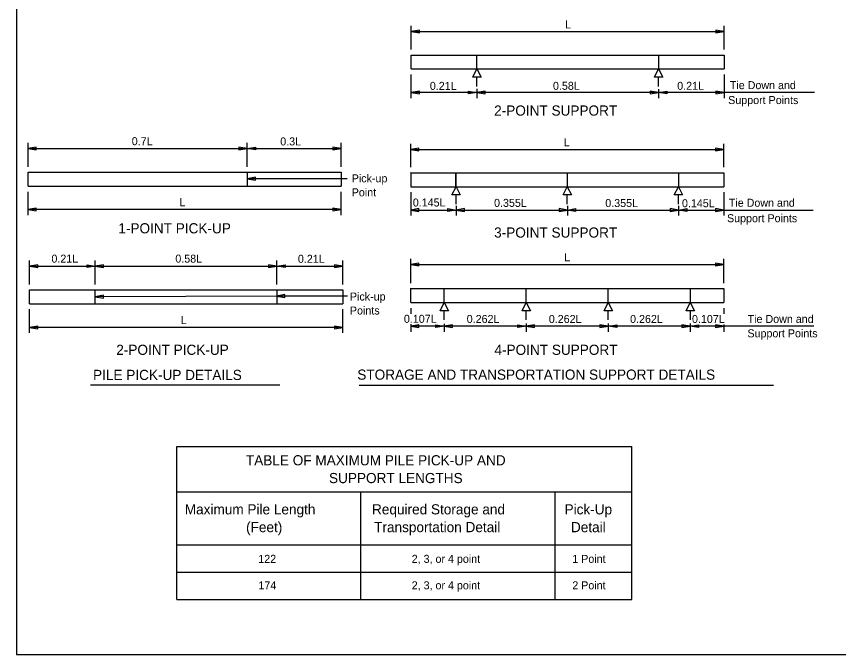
# Model space of a CAD drawing. Extents: x 120462 to 120592, y 120515 to 120635.
# Drawn here: x 120521.21 to 120541.92, y 120603.22 to 120619.3 of the extents above; entities that cross this region are included whole.
import ezdxf

# ---------------------------------------------------------------- set-up
doc = ezdxf.new("R2010")
doc.units = 0
for name, color, linetype in [('ActivePts-ConstElements', 7, 'Continuous'), ('AdhocPoint_dp', 7, 'Continuous'), ('Border', 7, 'Continuous'), ('PlotBorder_dp', 7, 'Continuous')]:
    doc.layers.add(name, color=color, linetype=linetype)

msp = doc.modelspace()

# ---------------------------------------------------------------- linework, layer by layer
at = {"layer": 'ActivePts-ConstElements'}
msp.add_lwpolyline([(120521.209, 120603.217), (120562.259, 120603.217), (120562.259, 120629.163), (120521.209, 120629.163)], close=True, dxfattribs=at)
at = {"layer": 'AdhocPoint_dp'}
for p, q in [((120531.151, 120618.464), (120531.151, 120619.058)), ((120531.151, 120618.918), (120539.041, 120618.918)), ((120539.041, 120618.464), (120539.041, 120619.058)), ((120531.151, 120617.24), (120531.151, 120617.836)), ((120539.041, 120617.836), (120539.041, 120617.24)), ((120532.81, 120617.536), (120532.81, 120617.768)), ((120537.386, 120617.536), (120537.386, 120617.768)), ((120532.808, 120617.47), (120532.808, 120617.24)), ((120537.385, 120617.468), (120537.385, 120617.24)), ((120541.313, 120617.38), (120531.151, 120617.38)), ((120521.501, 120615.509), (120521.501, 120616.109)), ((120521.501, 120615.969), (120529.39, 120615.969)), ((120527.023, 120615.509), (120527.023, 120616.109)), ((120529.39, 120615.509), (120529.39, 120616.109)), ((120531.141, 120615.496), (120531.141, 120616.084)), ((120539.03, 120615.496), (120539.03, 120616.084)), ((120531.141, 120615.944), (120539.03, 120615.944)), ((120531.141, 120615.356), (120531.141, 120615.364)), ((120532.283, 120615.356), (120532.283, 120615.359)), ((120535.085, 120615.356), (120535.085, 120615.362)), ((120529.54, 120615.208), (120527.023, 120615.208)), ((120521.501, 120614.291), (120521.501, 120614.88)), ((120529.39, 120614.291), (120529.39, 120614.881)), ((120531.141, 120614.867), (120531.141, 120614.279)), ((120532.286, 120614.567), (120532.286, 120614.799)), ((120535.086, 120614.567), (120535.086, 120614.799)), ((120537.888, 120614.567), (120537.888, 120614.799)), ((120539.03, 120614.867), (120539.03, 120614.279)), ((120532.285, 120614.522), (120532.285, 120614.279)), ((120535.088, 120614.522), (120535.088, 120614.279)), ((120537.89, 120614.522), (120537.89, 120614.279)), ((120529.39, 120614.431), (120521.501, 120614.431)), ((120531.141, 120614.419), (120541.285, 120614.419)), ((120521.538, 120612.545), (120521.538, 120613.144)), ((120523.195, 120612.545), (120523.195, 120613.144)), ((120527.771, 120612.545), (120527.771, 120613.144)), ((120529.428, 120612.545), (120529.428, 120613.144)), ((120531.141, 120612.578), (120531.141, 120613.185)), ((120539.03, 120612.578), (120539.03, 120613.185)), ((120521.538, 120613.004), (120529.428, 120613.004)), ((120531.141, 120613.045), (120539.03, 120613.045)), ((120531.141, 120612.438), (120531.141, 120612.446)), ((120535.085, 120612.438), (120535.085, 120612.445)), ((120527.761, 120612.252), (120523.195, 120612.235)), ((120529.546, 120612.252), (120527.761, 120612.252)), ((120532.283, 120612.438), (120532.283, 120612.441)), ((120521.538, 120611.321), (120521.538, 120611.917)), ((120529.428, 120611.321), (120529.428, 120611.917)), ((120531.141, 120611.95), (120531.141, 120611.801)), ((120531.986, 120611.65), (120531.986, 120611.881)), ((120534.053, 120611.65), (120534.053, 120611.881)), ((120536.12, 120611.65), (120536.12, 120611.881)), ((120538.188, 120611.65), (120538.188, 120611.881)), ((120539.03, 120611.95), (120539.03, 120611.799)), ((120529.428, 120611.461), (120521.538, 120611.461)), ((120531.141, 120611.545), (120531.141, 120611.353)), ((120541.298, 120611.493), (120531.141, 120611.493)), ((120531.985, 120611.548), (120531.985, 120611.353)), ((120531.985, 120611.418), (120531.985, 120611.353)), ((120534.051, 120611.561), (120534.051, 120611.353)), ((120536.118, 120611.561), (120536.118, 120611.353)), ((120538.185, 120611.559), (120538.185, 120611.353)), ((120539.03, 120611.531), (120539.03, 120611.353)), ((120536.121, 120611.353), (120536.121, 120611.353)), ((120527.847, 120610.008), (120523.078, 120610.008)), ((120529.843, 120610.002), (120540.285, 120610.002)), ((120525.253, 120608.457), (120536.712, 120608.457)), ((120525.253, 120604.606), (120525.253, 120608.457)), ((120536.712, 120604.606), (120536.712, 120608.457)), ((120525.253, 120607.321), (120536.712, 120607.321)), ((120529.883, 120604.606), (120529.883, 120607.321)), ((120534.778, 120604.606), (120534.778, 120607.321)), ((120525.253, 120605.985), (120536.712, 120605.985)), ((120525.253, 120605.296), (120536.712, 120605.296)), ((120525.253, 120604.606), (120536.712, 120604.606))]:
    msp.add_line(p, q, dxfattribs=at)
for points in [[(120531.151, 120618.918), (120531.36, 120618.883), (120531.36, 120618.953)], [(120539.041, 120618.918), (120538.833, 120618.953), (120538.833, 120618.883)], [(120532.808, 120617.976), (120532.913, 120617.768), (120532.703, 120617.768)], [(120537.385, 120617.976), (120537.49, 120617.768), (120537.28, 120617.768)], [(120531.151, 120617.38), (120531.36, 120617.345), (120531.36, 120617.415)], [(120532.808, 120617.38), (120532.6, 120617.345), (120532.6, 120617.415)], [(120532.808, 120617.38), (120533.016, 120617.345), (120533.016, 120617.415)], [(120537.385, 120617.38), (120537.176, 120617.415), (120537.176, 120617.345)], [(120537.385, 120617.38), (120537.593, 120617.415), (120537.593, 120617.345)], [(120539.041, 120617.38), (120538.833, 120617.415), (120538.833, 120617.345)], [(120521.501, 120615.969), (120521.71, 120615.934), (120521.71, 120616.004)], [(120527.023, 120615.969), (120526.815, 120616.004), (120526.815, 120615.934)], [(120527.023, 120615.969), (120527.231, 120616.004), (120527.231, 120615.934)], [(120529.39, 120615.969), (120529.182, 120616.004), (120529.182, 120615.934)], [(120531.141, 120615.944), (120531.35, 120615.909), (120531.35, 120615.979)], [(120539.03, 120615.944), (120538.821, 120615.979), (120538.821, 120615.909)], [(120527.023, 120615.208), (120527.231, 120615.172), (120527.231, 120615.243)], [(120532.285, 120615.007), (120532.39, 120614.799), (120532.18, 120614.799)], [(120535.085, 120615.007), (120535.19, 120614.799), (120534.98, 120614.799)], [(120537.886, 120615.007), (120537.991, 120614.799), (120537.781, 120614.799)], [(120521.501, 120614.431), (120521.71, 120614.396), (120521.71, 120614.466)], [(120529.39, 120614.431), (120529.182, 120614.466), (120529.182, 120614.396)], [(120531.141, 120614.419), (120531.35, 120614.384), (120531.35, 120614.454)], [(120532.285, 120614.419), (120532.076, 120614.384), (120532.076, 120614.454)], [(120532.285, 120614.419), (120532.493, 120614.384), (120532.493, 120614.454)], [(120535.088, 120614.419), (120534.88, 120614.454), (120534.88, 120614.384)], [(120535.088, 120614.419), (120535.296, 120614.454), (120535.296, 120614.384)], [(120537.89, 120614.419), (120537.681, 120614.454), (120537.681, 120614.384)], [(120537.89, 120614.419), (120538.098, 120614.454), (120538.098, 120614.384)], [(120539.03, 120614.419), (120538.821, 120614.454), (120538.821, 120614.384)], [(120531.141, 120613.045), (120531.35, 120613.01), (120531.35, 120613.081)], [(120539.03, 120613.045), (120538.821, 120613.081), (120538.821, 120613.01)], [(120521.538, 120613.004), (120521.746, 120612.969), (120521.746, 120613.04)], [(120523.195, 120613.004), (120522.987, 120612.969), (120522.987, 120613.04)], [(120523.195, 120613.004), (120523.403, 120612.969), (120523.403, 120613.04)], [(120527.771, 120613.004), (120527.563, 120613.04), (120527.563, 120612.969)], [(120527.771, 120613.004), (120527.98, 120613.04), (120527.98, 120612.969)], [(120529.428, 120613.004), (120529.22, 120613.04), (120529.22, 120612.969)], [(120523.195, 120612.235), (120523.403, 120612.2), (120523.403, 120612.271)], [(120527.761, 120612.252), (120527.97, 120612.216), (120527.97, 120612.287)], [(120531.985, 120612.09), (120532.09, 120611.881), (120531.88, 120611.881)], [(120534.051, 120612.09), (120534.156, 120611.881), (120533.946, 120611.881)], [(120536.118, 120612.09), (120536.223, 120611.881), (120536.013, 120611.881)], [(120538.186, 120612.09), (120538.291, 120611.881), (120538.081, 120611.881)], [(120521.538, 120611.461), (120521.746, 120611.426), (120521.746, 120611.496)], [(120529.428, 120611.461), (120529.22, 120611.496), (120529.22, 120611.426)], [(120531.141, 120611.493), (120531.35, 120611.458), (120531.35, 120611.528)], [(120531.985, 120611.493), (120531.776, 120611.458), (120531.776, 120611.528)], [(120531.985, 120611.493), (120532.193, 120611.458), (120532.193, 120611.528)], [(120534.051, 120611.493), (120533.843, 120611.458), (120533.843, 120611.528)], [(120534.051, 120611.493), (120534.26, 120611.458), (120534.26, 120611.528)], [(120536.118, 120611.493), (120535.91, 120611.528), (120535.91, 120611.458)], [(120536.125, 120611.493), (120536.333, 120611.528), (120536.333, 120611.458)], [(120538.185, 120611.493), (120537.976, 120611.528), (120537.976, 120611.458)], [(120538.185, 120611.493), (120538.393, 120611.528), (120538.393, 120611.458)], [(120539.03, 120611.493), (120538.821, 120611.528), (120538.821, 120611.458)]]:
    msp.add_lwpolyline(points, close=True, dxfattribs=at)
at = {"layer": 'PlotBorder_dp'}
for p, q in [((120531.151, 120618.324), (120539.041, 120618.324)), ((120531.151, 120617.976), (120531.151, 120618.324)), ((120532.808, 120617.976), (120532.808, 120618.324)), ((120537.385, 120618.324), (120537.385, 120617.976)), ((120539.041, 120618.324), (120539.041, 120617.976)), ((120531.151, 120617.976), (120539.041, 120617.976)), ((120521.501, 120615.369), (120529.39, 120615.369)), ((120521.501, 120615.021), (120521.501, 120615.369)), ((120527.023, 120615.369), (120527.023, 120615.021)), ((120529.39, 120615.369), (120529.39, 120615.021)), ((120531.141, 120615.356), (120539.03, 120615.356)), ((120531.141, 120615.356), (120531.141, 120615.007)), ((120532.283, 120615.007), (120532.283, 120615.356)), ((120532.285, 120615.007), (120532.285, 120615.356)), ((120535.085, 120615.356), (120535.085, 120615.007)), ((120535.233, 120615.356), (120539.03, 120615.356)), ((120537.886, 120615.356), (120537.886, 120615.007)), ((120539.03, 120615.356), (120539.03, 120615.007)), ((120521.501, 120615.021), (120529.39, 120615.021)), ((120531.141, 120615.007), (120539.03, 120615.007)), ((120521.538, 120612.405), (120529.428, 120612.405)), ((120521.538, 120612.057), (120521.538, 120612.405)), ((120523.195, 120612.057), (120523.195, 120612.405)), ((120527.771, 120612.405), (120527.771, 120612.057)), ((120529.428, 120612.405), (120529.428, 120612.057)), ((120531.141, 120612.438), (120539.03, 120612.438)), ((120531.141, 120612.09), (120531.141, 120612.438)), ((120531.985, 120612.09), (120531.985, 120612.438)), ((120534.051, 120612.09), (120534.051, 120612.438)), ((120535.233, 120612.438), (120539.03, 120612.438)), ((120536.118, 120612.09), (120536.118, 120612.438)), ((120538.186, 120612.438), (120538.186, 120612.09)), ((120539.03, 120612.438), (120539.03, 120612.09)), ((120521.538, 120612.057), (120529.428, 120612.057)), ((120531.141, 120612.09), (120539.03, 120612.09))]:
    msp.add_line(p, q, dxfattribs=at)

# ---------------------------------------------------------------- texts
at = {"layer": 'AdhocPoint_dp'}
for s, height, p in [('Pick-up ', 0.2016, (120529.656, 120615.117)), ('Point', 0.2016, (120529.656, 120614.765)), ('Pick-up ', 0.2016, (120529.61, 120612.138)), ('Points', 0.2016, (120529.61, 120611.786)), ('TABLE OF MAXIMUM PILE PICK-UP AND', 0.256, (120526.99, 120607.985)), ('SUPPORT LENGTHS', 0.256, (120529.084, 120607.537)), ('Maximum Pile Length', 0.256, (120525.45, 120606.749)), ('Required Storage and', 0.256, (120530.168, 120606.749)), ('Pick-Up', 0.256, (120535.018, 120606.749)), ('(Feet)', 0.256, (120526.994, 120606.301)), ('Transportation Detail  ', 0.256, (120530.221, 120606.301)), ('Detail', 0.256, (120535.179, 120606.3))]:
    msp.add_text(s, height=height, dxfattribs=at).set_placement(p)
at = {"layer": 'Border'}
for s, height, p in [('L', 0.202, (120535.031, 120618.994)), ('0.21L', 0.2016, (120531.624, 120617.447)), ('0.58L', 0.2016, (120534.726, 120617.448)), ('0.21L', 0.2016, (120537.856, 120617.448)), ('Tie Down and', 0.2016, (120539.182, 120617.465)), ('Support Points', 0.2016, (120539.14, 120617.089)), ('2-POINT SUPPORT', 0.256, (120533.244, 120616.798)), ('0.7L', 0.2016, (120524.114, 120616.053)), ('0.3L', 0.2016, (120527.855, 120616.047)), ('L', 0.202, (120535.001, 120616.024)), ('L', 0.202, (120525.318, 120614.516)), ('0.145L', 0.2016, (120531.195, 120614.508)), ('0.355L', 0.2016, (120533.242, 120614.499)), ('0.355L', 0.2016, (120536.044, 120614.494)), ('0.145L', 0.2016, (120537.976, 120614.49)), ('Tie Down and', 0.2016, (120539.156, 120614.502)), ('Support Points', 0.2016, (120539.111, 120614.112)), ('1-POINT PICK-UP', 0.256, (120523.777, 120613.831)), ('3-POINT SUPPORT', 0.256, (120533.244, 120613.724)), ('0.21L', 0.2016, (120522.09, 120613.093)), ('0.58L', 0.2016, (120525.212, 120613.093)), ('0.21L', 0.2016, (120528.3, 120613.089)), ('L', 0.202, (120535.01, 120613.125)), ('L', 0.202, (120525.349, 120611.545)), ('0.107L', 0.2016, (120530.97, 120611.577)), ('0.262L', 0.2016, (120532.553, 120611.573)), ('0.262L', 0.2016, (120534.621, 120611.573)), ('0.262L', 0.2016, (120536.669, 120611.573)), ('0.107L', 0.2016, (120538.229, 120611.572)), ('Tie Down and', 0.2016, (120539.63, 120611.573)), ('Support Points', 0.2016, (120539.625, 120611.211)), ('2-POINT PICK-UP', 0.256, (120523.724, 120610.769)), ('4-POINT SUPPORT', 0.256, (120533.252, 120610.769)), ('PILE PICK-UP DETAILS', 0.256, (120523.139, 120610.136)), ('STORAGE AND TRANSPORTATION SUPPORT DETAILS', 0.256, (120529.796, 120610.143)), ('122', 0.2016, (120527.302, 120605.528)), ('2, 3, or 4 point', 0.2016, (120531.167, 120605.528)), ('1 Point', 0.2016, (120535.213, 120605.528)), ('174', 0.2016, (120527.306, 120604.861)), ('2, 3, or 4 point', 0.2016, (120531.167, 120604.861)), ('2 Point', 0.2016, (120535.213, 120604.861))]:
    msp.add_text(s, height=height, dxfattribs=at).set_placement(p)

doc.saveas('drawing.dxf')
